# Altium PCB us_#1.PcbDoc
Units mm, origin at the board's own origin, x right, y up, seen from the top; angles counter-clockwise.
Board outline 35.5 x 50 mm, 2 copper layers (Top Layer, Bottom Layer); 23 components, 13 nets, 121 pads, 7 vias.
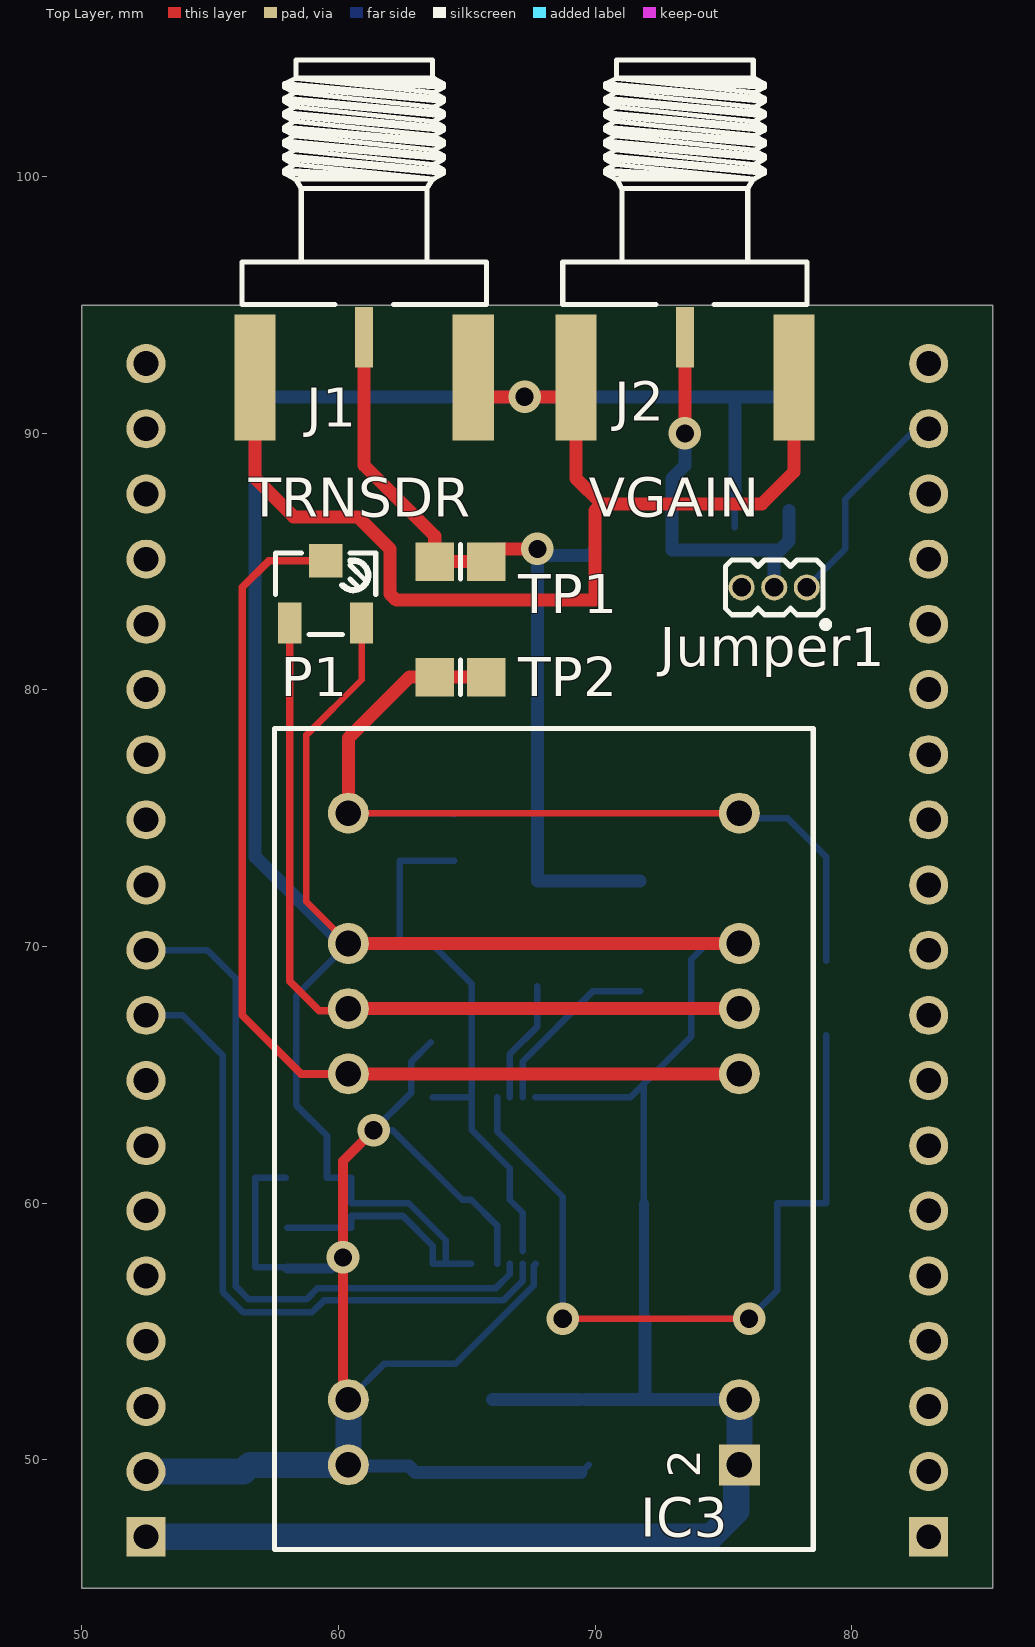
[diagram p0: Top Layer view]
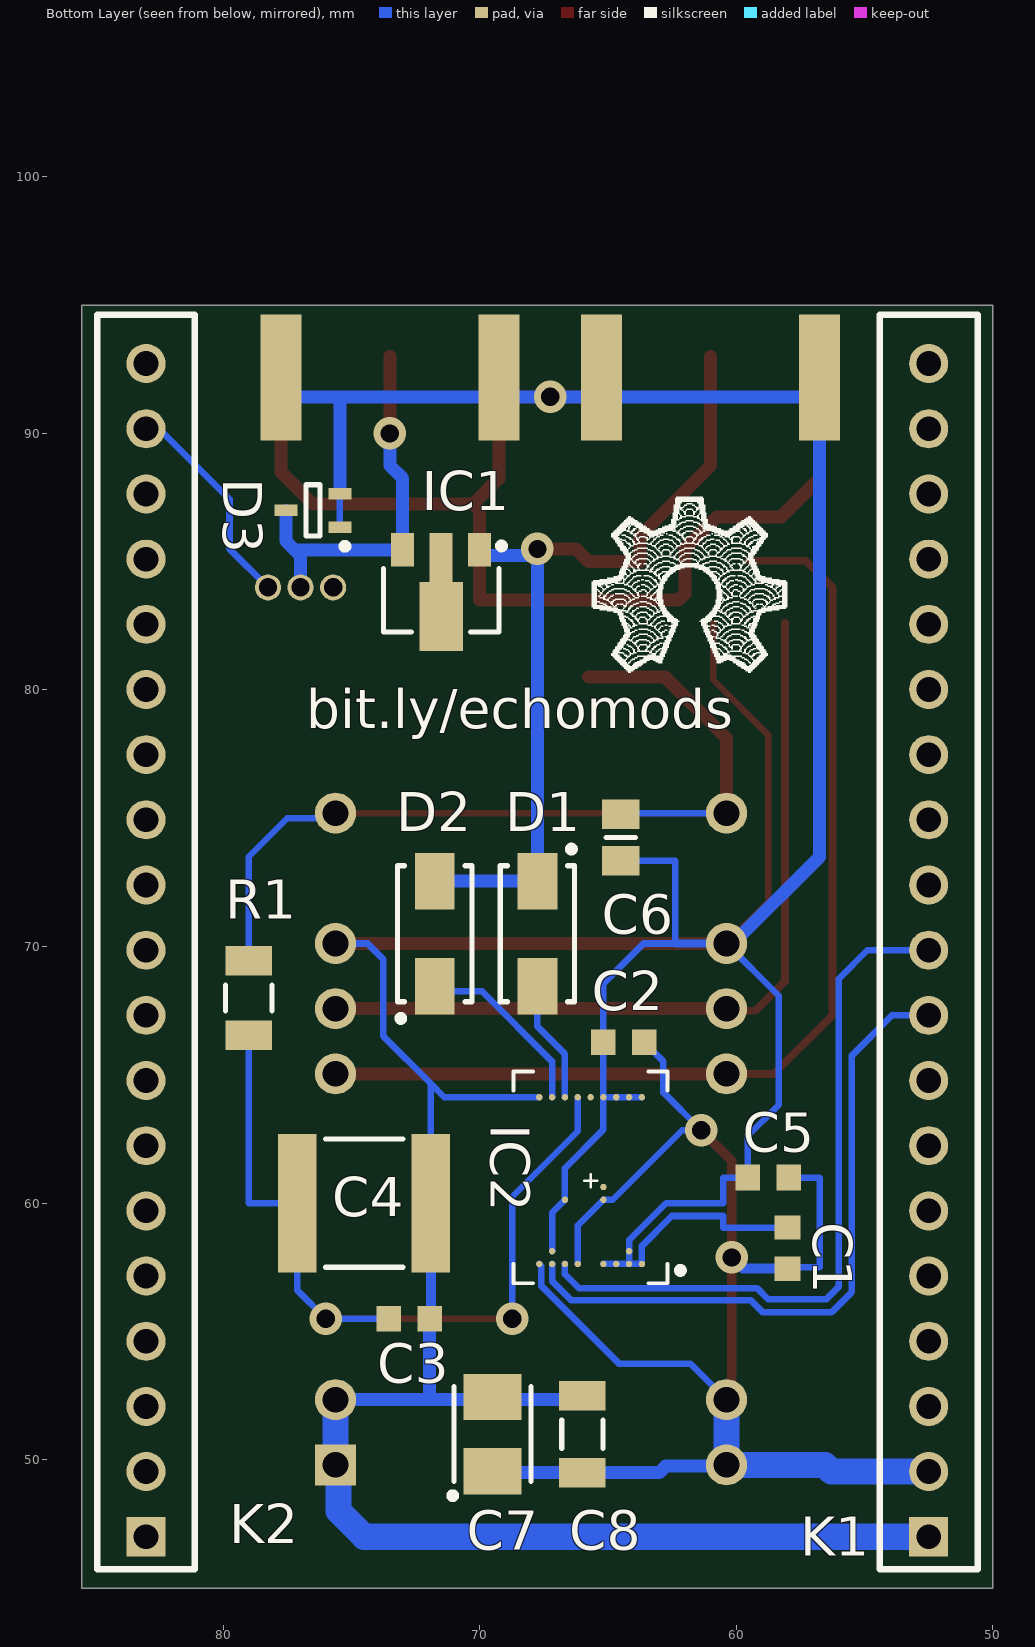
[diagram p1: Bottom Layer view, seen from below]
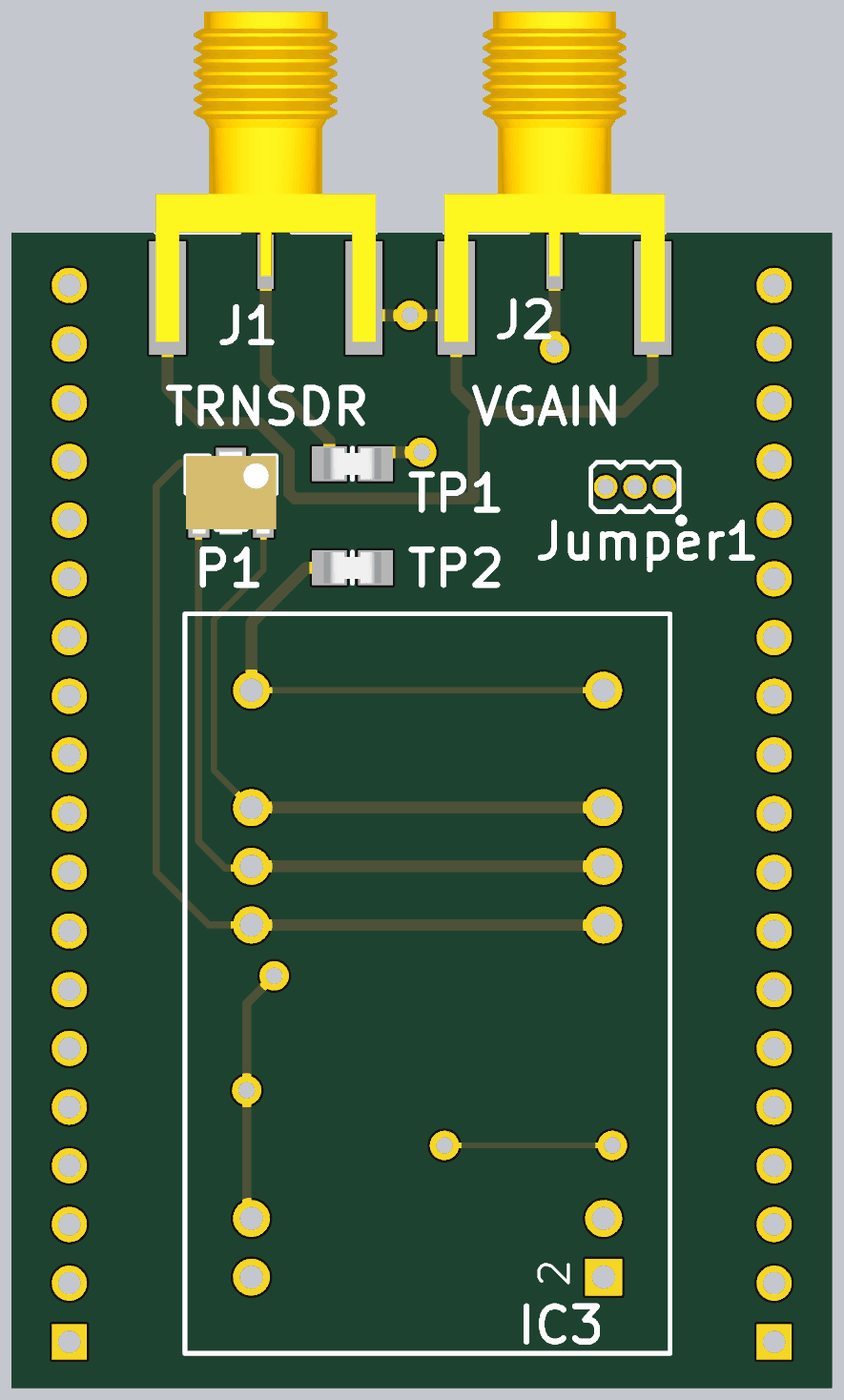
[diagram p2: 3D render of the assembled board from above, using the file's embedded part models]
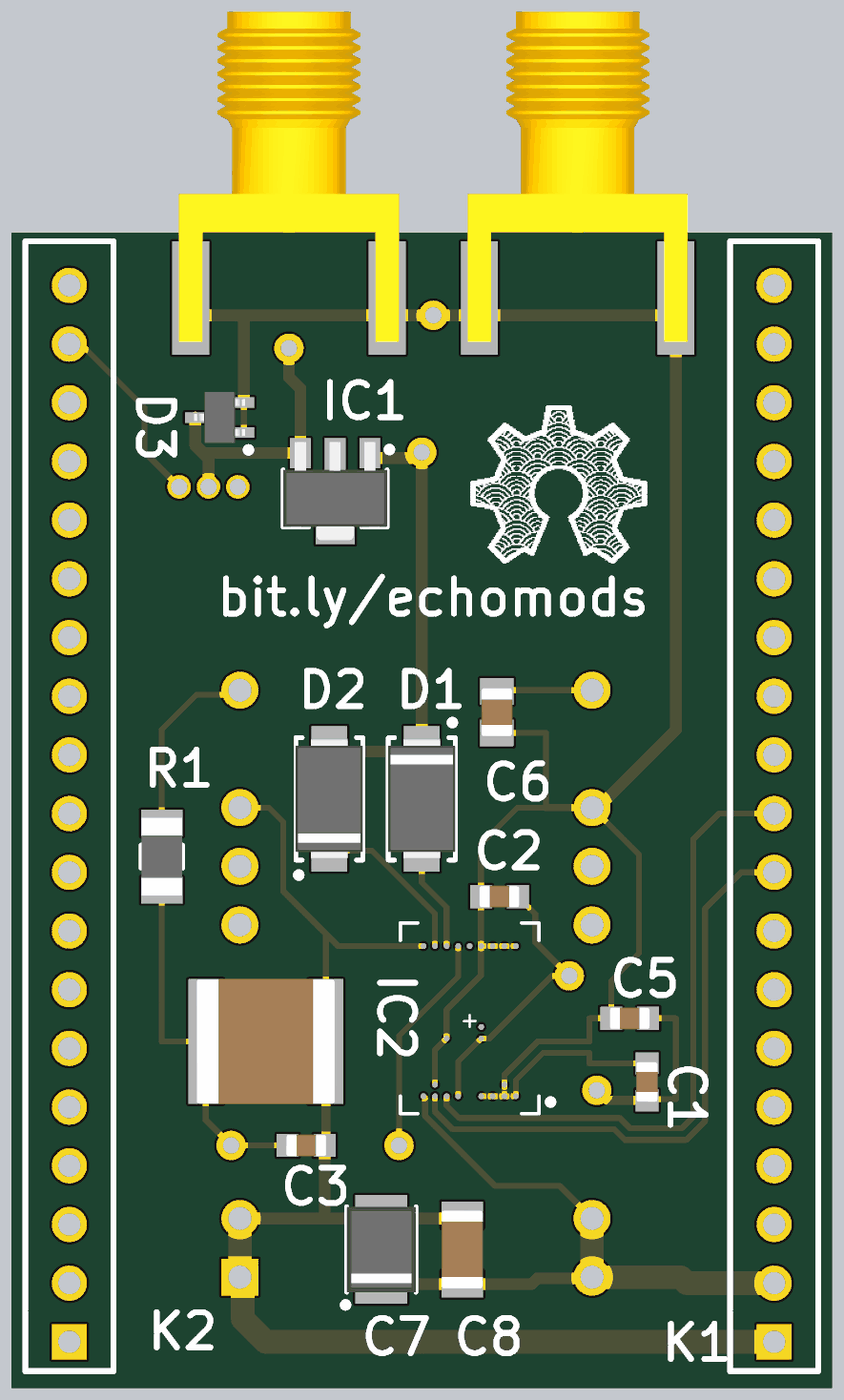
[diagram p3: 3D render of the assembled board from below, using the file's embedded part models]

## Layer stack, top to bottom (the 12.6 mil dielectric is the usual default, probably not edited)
Top Solder: solder mask 0.0102, Solder Resist, Dk 3.5
Top Layer: signal copper 0.0356
Dielectric 1: dielectric 0.32, FR-4, Dk 4.8
Bottom Layer: signal copper 0.0356
Bottom Solder: solder mask 0.0102, Solder Resist, Dk 3.5

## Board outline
50,45 85.5,45 85.5,95 50,95

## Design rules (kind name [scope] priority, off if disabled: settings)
Clearance [All] p1: gap=0.178
MinimumSolderMaskSliver [All] p1 off: minsoldermaskwidth=0.2
PolygonConnect [All] p1: connectstyle=Relief reliefconductorwidth=0.254 reliefentries=4 polygonreliefangle="90 Angle" airgapwidth=0.254
RoutingVias [All] p1: holewidth=0.711 width=1.27 viastyle="Through Hole" minholewidth=0.711 minwidth=1.27 maxholewidth=0.711 maxwidth=1.27
SilkToSilkClearance [All] p1 off: silktosilkclearance=0.254
SilkToSolderMaskClearance [IsPad] p1 off: minsilkscreentomaskgap=0.2 clearancetoexposedcopper=TRUE
SolderMaskExpansion [All] p1: expansion=0.102
Width [All] p1: maxlimit=1.016 minlimit=0.254 preferedwidth=0.254 minimp=50.000000 maximp=50.000000 favimp=50.000000
27 further rules are at their usual default settings.

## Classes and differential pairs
net class RF: NetD1_1 NetD3_3

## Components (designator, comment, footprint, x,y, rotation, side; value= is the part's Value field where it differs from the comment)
C1 "100nF" CAPC1608X87N 58,58.25 r270 bottom
C2 "100nF" CAPC1608X87N 64.389,66.269 r180 bottom
C3 "100nF" CAPC1608X87N 72.75,55.5 r0 bottom
C4 "1uF" CAPC5650X165N 74.5,60 r0 bottom
C5 "100nF" CAPC1608X87N 58.75,61 r180 bottom
C6 "4.7nF" CAPC2012X110N 64.5,74.25 r90 bottom
C7 "10uF" CAPMP3528X210N 69.5,51 r90 bottom
C8 "47uF" CAPC3216X180N 66,51 r270 bottom
D1 "ES1D" DIOM5027X244N 67.75,70.5 r270 bottom
D2 "ES1D" DIOM5027X244N 71.75,70.5 r90 bottom
D3 "BAT64-04W" SOT65P210X100-3N 76.5,87 r0 bottom
IC1 "MD0100N8-G" SOT89 71.5,83.5 r270 bottom
IC2 "HV7360LA-G" HV7360_BGA 63.676,64.13 r0 bottom
IC3 "R05-100B" PWS_RECOM_R05-100B 68,62.5 r90 top
J1 "SMA" AMPHENOL_132357-11 61,93.75 r270 top
J2 "SMA" AMPHENOL_132357-11 73.5,93.75 r270 top
Jumper1 "Family" SULLINS_GRPB031VWVN 78.25,84 r180 top
K1 "PLS_2.54mm-19" PLS_2.54mm-19 52.5,47 r180 bottom
K2 "PLS_2.54mm-19" PLS_2.54mm-19 83,47 r180 bottom
P1 "5k" TRIM_BOURNS_3223W 59.5,83.75 r0 top
R1 "4k7" RESC3216X65N 79,68 r90 bottom
TP1 "Test Point" NICOMATIC_C12000B 64.75,85 r0 top
TP2 "Test Point" NICOMATIC_C12000B 64.75,80.5 r180 top

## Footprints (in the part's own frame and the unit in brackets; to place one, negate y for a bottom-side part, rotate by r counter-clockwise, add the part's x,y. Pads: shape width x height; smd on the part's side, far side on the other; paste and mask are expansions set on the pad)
AMPHENOL_132357-11 [mm]
  rect 2.35x0.7 smd: 1(0,0)
  rect 4.9x1.6 smd: 2(1.575,4.25) 2(1.575,-4.25)
  rect 4.9x1.6 smd far side: 2(1.575,4.25) 2(1.575,-4.25)
  silkscreen extent -10.81,-4.76 -1.28,4.76, body extent -10.8,-4.76 3.48,4.76, height 4.08
CAPC1608X87N [mm]
  rect 0.95x1 smd: 1(-0.8,0) 2(0.8,0)
  body extent -0.87,-0.47 0.88,0.48, height 0.87
CAPC2012X110N [mm]
  rect 1.15x1.45 smd: 1(-0.9,0) 2(0.9,0)
  silkscreen extent 0,-0.58 0,0.58, body extent -1.05,-0.67 1.05,0.68, height 1.1
CAPC3216X180N [mm]
  rect 1.15x1.8 smd: 1(-1.5,0) 2(1.5,0)
  silkscreen extent -0.55,-0.8 0.55,0.8, body extent -1.7,-0.9 1.7,0.9, height 1.8
CAPC5650X165N [mm]
  rect 1.5x5.4 smd: 1(-2.6,0) 2(2.6,0)
  silkscreen extent -1.5,-2.5 1.5,2.5, body extent -3,-2.7 3,2.7, height 1.65
CAPMP3528X210N [mm]
  rect 1.8x2.25 smd: 1(-1.45,0) 2(1.45,0)
  silkscreen extent -2.52,-1.5 1.85,1.68, body extent -1.85,-1.5 1.85,1.5, height 2.1
DIOM5027X244N [mm]
  rect 2.2x1.55 smd: 1(-2.05,0) 2(2.05,0)
  silkscreen extent -3.42,-1.45 2.65,1.45, body extent -2.6,-1.45 2.6,1.45, height 2.44
HV7360_BGA [mm]
  round 0.25 smd: A1(0,6.5) A2(0.5,6.5) A3(1,6.5) A4(1.5,6.5) A6(2.5,6.5) A7(3,6.5) A8(3.5,6.5) A9(4,6.5) B2(0.5,6) B8(3.5,6) F4(1.5,4) F7(3,4) G4(1.5,3.5) P1(0,0) P2(0.5,0) P3(1,0) P4(1.5,0) P5(2,0) P6(2.5,0) P7(3,0) P8(3.5,0) P9(4,0)
  silkscreen extent -1.6,-1 5,7.25
NICOMATIC_C12000B [mm]
  rect 1.5x1.5 smd: 1(-1,0) 1(1,0)
  silkscreen extent 0,-0.67 0,0.67, body extent -1.25,-0.67 1.25,0.68, height 1.5
PLS_2.54mm-19 [mil] "soldering pads"
  rect 60x60 hole 38: 1(0,0)
  round 60 hole 38: 2(0,100) 3(0,200) 4(0,300) 5(0,400) 6(0,500) 7(0,600) 8(0,700) 9(0,800) 10(0,900) 11(0,1000) 12(0,1100) 13(0,1200) 14(0,1300) 15(0,1400) 16(0,1500) 17(0,1600) 18(0,1700) 19(0,1800)
  silkscreen extent -75,-50 75,1875
PWS_RECOM_R05-100B [mm]
  rect 1.6x1.6 hole 1: 2(-12.7,-7.62)
  round 1.6 hole 1: 3(-10.16,-7.62) 8(2.54,-7.62) 9(5.08,-7.62) 10(7.62,-7.62) 12(12.7,-7.62) 13(12.7,7.62) 15(7.62,7.62) 16(5.08,7.62) 17(2.54,7.62) 22(-10.16,7.62) 23(-12.7,7.62)
  silkscreen extent -16,-10.5 16,10.5, body extent -16,-10.5 16,10.5, height 9.4
RESC3216X65N [mm]
  rect 1.15x1.8 smd: 1(-1.45,0) 2(1.45,0)
  silkscreen extent -0.5,-0.9 0.5,0.9, body extent -1.67,-0.87 1.68,0.88, height 0.65
SOT65P210X100-3N [mm]
  rect 0.9x0.45 smd: 1(-1.05,0.65) 2(-1.05,-0.65) 3(1.05,0)
  silkscreen extent -1.37,-1 0.28,1.52, body extent -1.1,-1.1 1.1,1.1, height 1
SOT89 [mm]
  rect 1.3x0.9 smd: 1(-1.965,1.5) 3(-1.965,-1.5)
  rect 1.9x0.9 smd: 2(-1.665,0)
  rect 2.7x1.7 smd: 2(0.635,0)
  silkscreen extent -2.24,-2.25 1.24,2.47, body extent -2.44,-2.25 1.81,2.25, height 1.6
SULLINS_GRPB031VWVN [mil]
  round 40 hole 28: 1(0,0) 2(50,0) 3(100,0)
  silkscreen extent -33,-42 125,61
TRIM_BOURNS_3223W [mm]
  rect 0.9x1.6 smd: 1(-1.4,-1.14) 3(1.4,-1.14)
  rect 1.3x1.3 smd: 2(0,1.29)
  silkscreen extent -1.95,-1.59 1.95,1.59, body extent -1.95,-1.81 1.95,1.81, height 4.16

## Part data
C1 C2 C3 C5: library part CC0603_100NF_50V_10%_X7R, "Non-polarised capacitor"
C4: library part CC2220_1UF_200V_10%_X7R, "Non-polarised capacitor"
C6: library part CC0805_4.7NF_250V_10%_X7R, "Non-polarised capacitor"
C7: library part CTE3528-21_10UF_16V_10%_LESR0800, "Polarised capacitor"
C8: library part CC1206_47UF_25V_20%_X5R, "Non-polarised capacitor"
D1 D2: "Diode"
D3: "Serial Diode"
IC1: "3-Ultra-Sound HV Switch 1=A 2=COM 3=B"
IC3: "Power Supply"
J1 J2: library part AMPHENOL_132357-11
Jumper1: library part "Connector 3 Male", "Connector 3 Male"
P1: library part TRIM_11T_5K_BOURNS_3223W-1-502E, "Trimming Potentiometer"
R1: library part R1206_4K7_1%_0.25W_100PPM, "Resistor - 1%"
TP1 TP2: library part NICOMATIC_C12000B

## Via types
v1: diameter 1.27, hole 0.711, Top Layer to Bottom Layer, 7 vias

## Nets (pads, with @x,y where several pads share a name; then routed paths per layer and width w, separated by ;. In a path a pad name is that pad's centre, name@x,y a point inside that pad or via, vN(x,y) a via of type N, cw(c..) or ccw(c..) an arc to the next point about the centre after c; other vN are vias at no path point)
AGND: C1.1 C2.1 C3.1 C4.1 C5.1 C6.1 C7.2 C8.1 D3.1 D3.2 IC2.A1 IC2.A2 IC2.A3 IC2.A4 IC2.B2 IC2.B8 IC2.F7 IC2.P1 IC2.P2 IC2.P3 IC2.P4 IC2.P9 IC3.2 IC3.3 IC3.10 IC3.15 J1.2 J2.2 K1.1 P1.3 | length 233.2
  Top Layer w0.254: IC3.15 58.75,71.75 58.75,78.25 60.9,80.4 P1.3
  Top Layer w0.508: J1.2@56.75,92.175 56.75,88.25 58.25,86.75 60.75,86.75 62,85.5 62,83.75 62.25,83.5 70,83.5 70,87 70.25,87.25 ; IC3.15 IC3.10 ; J1.2@65.25,91.425 69.25,91.425 69.25,88.25 70.25,87.25 ; J2.2@77.75,91.425 77.75,88.5 76.5,87.25 70.25,87.25
  Bottom Layer w0.254: C1.1 60.5,59.05 60.5,59.5 62.509,59.5 63.676,58.333 IC2.A1 IC2.A2 ; IC3.15 58.344,68.084 58.344,63.83 59.55,62.624 C5.1 60.5,61 60.5,60 62.733,60 64.176,58.556 IC2.B2 IC2.A2 ; IC2.P1 IC2.P2 IC2.P3 IC2.P4 ; C6.1 62.38,73.35 62.38,70.12 63.611,70.12 65.189,68.542 C2.1 65.189,62.852 66.676,61.365 IC2.F7 67.176,59.63 IC2.B8 ; IC2.A4 IC2.A3 IC2.A2 ; IC2.P9 71.38,64.13 71.9,64.65 ; C3.1@71.9,55.55 C3.1 ; C4.1 71.9,64.65 ; D3.1 D3.2 ; IC3.10 74.37,70.12 73.75,69.5 73.75,66.5 71.9,64.65
  Bottom Layer w0.305: IC3.15 62.38,70.12
  Bottom Layer w0.381: C3.1@71.9,55.55 C4.1
  Bottom Layer w0.508: IC3.15@60.13,70.12 56.75,73.5 56.75,91.425 75.45,91.425 ; C8.1@66,52.34 C7.2@69.39,52.34 ; C7.2@69.61,52.34 IC3.3 ; 71.95,52.45 C3.1 ; D3.2 75.45,91.425 ; J2.2@77.75,91.425 75.45,91.425
  Bottom Layer w1.016: K1.1 74.5,47 75.5,48 75.5,49.68 IC3.2 IC3.3
  other v1: 67.25,91.425
HVOUT: C6.2 IC3.12 IC3.13 R1.2 TP2.1 | length 36.8
  Top Layer w0.254: IC3.13 IC3.12
  Top Layer w0.508: IC3.13 60.38,78.12 62.76,80.5 63.75,80.5 TP2.1@65.75,80.5
  Bottom Layer w0.254: IC3.13 64.45,75.2 C6.2 ; IC3.12 75.82,75 77.5,75 79,73.5 R1.2
NetC3_2: C3.2 C4.2 IC2.P6 R1.1 | length 32.8
  Top Layer w0.254: v1(68.734,55.5) v1(76,55.5)
  Bottom Layer w0.254: IC2.P6 66.176,62.805 68.734,60.247 v1(68.734,55.5) ; C3.2 v1(76,55.5) 77.1,56.6 C4.2 79,60 R1.1
NetD1_1: D1.1 D2.2 IC1.1 J1.1 TP1.1 | length 32.4
  Top Layer w0.508: J1.1@61,93 61,88.75 63.75,86 63.75,85 65.75,85 66.25,85.5 v1(67.75,85.5)
  Bottom Layer w0.508: IC1.1 69.785,85.25 67.75,85.25 D1.1 D2.2
NetD1_2: D1.2 IC2.P7 | length 4.8
  Bottom Layer w0.254: IC2.P7 66.676,65.813 67.75,66.886 D1.2
NetD2_1: D2.1 IC2.P8 | length 7.1
  Bottom Layer w0.254: IC2.P8 67.176,65.525 69.901,68.25 D2.1@71.75,68.25
NetD3_3: D3.3 IC1.3 J2.1 Jumper1.2 | length 15.2
  Top Layer w0.508: v1(73.5,90) J2.1@73.5,93
  Bottom Layer w0.508: v1(73.5,90) 73.5,88.75 73,88.25 IC1.3 77.215,85.465 ; Jumper1.2 76.98,85.23 77.215,85.465 ; D3.3 77.55,85.8 77.215,85.465
NetIC3_8: IC3.8 IC3.17 P1.2 | length 40.7
  Top Layer w0.305: P1.2 57.29,85.04 56.25,84 56.25,67.33 58.54,65.04 IC3.17
  Top Layer w0.508: IC3.17 IC3.8
NetIC3_9: IC3.9 IC3.16 P1.1 | length 32
  Top Layer w0.305: P1.1 58.1,68.65 59.25,67.5 60.3,67.5 IC3.16
  Top Layer w0.508: IC3.16 IC3.9
PULSE_A: IC2.A8 K1.9 | length 26
  Bottom Layer w0.254: K1.9 53.93,67.32 55.492,65.758 55.492,56.54 56.29,55.742 58.96,55.742 59.429,56.21 66.421,56.21 67.176,56.966 IC2.A8
PULSE_B: IC2.A7 K1.10 | length 27.7
  Bottom Layer w0.254: K1.10 54.89,69.86 56,68.75 56,56.75 56.5,56.25 58.75,56.25 59.193,56.693 66.142,56.693 66.676,57.228 IC2.A7
VDD_5V: C1.2 C2.2 C5.2 C7.1 C8.2 IC2.A6 IC2.A9 IC2.F4 IC3.22 IC3.23 K1.2 | length 61.1
  Top Layer w0.381: IC3.22 60.173,52.547 v1(60.173,57.887) 60.173,61.646 v1(61.366,62.84)
  Top Layer w1.016: K1.2 K1.2@52.54,49.5
  Bottom Layer w0.254: C5.2 56.75,61 56.75,57.5 57.95,57.5 C1.2 ; IC3.22 61.79,53.75 64.571,53.75 67.608,56.787 67.608,57.562 IC2.A9 ; C2.2 62.84,65.519 62.84,64.313 v1(61.366,62.84) 62.107,62.84 64.817,60.13 IC2.F4 66.176,59.13 IC2.A6 ; C7.1@69.45,49.5 C7.1 C7.1@69.75,49.8
  Bottom Layer w0.381: C1.2 v1@59.736,57.45
  Bottom Layer w0.508: IC3.23@60.43,49.75 62.75,49.75 63,49.5 C8.2 C7.1@69.45,49.5
  Bottom Layer w1.016: K1.2@52.46,49.5 K1.2 56.29,49.54 56.55,49.8 IC3.23 IC3.22
"VGA IN": Jumper1.1 K2.18 | length 7.9
  Bottom Layer w0.254: Jumper1.1 79.75,85.5 79.75,87.43 K2.18@82.5,90.18
pads on no net: IC1.2 IC2.G4 IC2.P5 Jumper1.3 K1.3 K1.4 K1.5 K1.6 K1.7 K1.8 K1.11 K1.12 K1.13 K1.14 K1.15 K1.16 K1.17 K1.18 K1.19 K2.1 K2.2 K2.3 K2.4 K2.5 K2.6 K2.7 K2.8 K2.9 K2.10 K2.11 K2.12 K2.13 K2.14 K2.15 K2.16 K2.17 K2.19

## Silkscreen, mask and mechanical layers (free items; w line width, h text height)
Top Overlay:
  text "TRNSDR" at 56.5,86.75 h1.52
  text "VGAIN" at 69.75,86.75 h1.52
Bottom Overlay:
  drawing of 1520 lines, arcs and shapes, not listed
  text "bit.ly/echomods" at 76.75,78.5 h1.52
Mechanical 1:
  lines w0.254: 50,45 50,95 85.5,95 85.5,91.375 85.5,86.125 85.5,82 85.5,75.75 85.5,64.25 85.5,58 85.5,53.875 85.5,48.625 85.5,45 50,45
